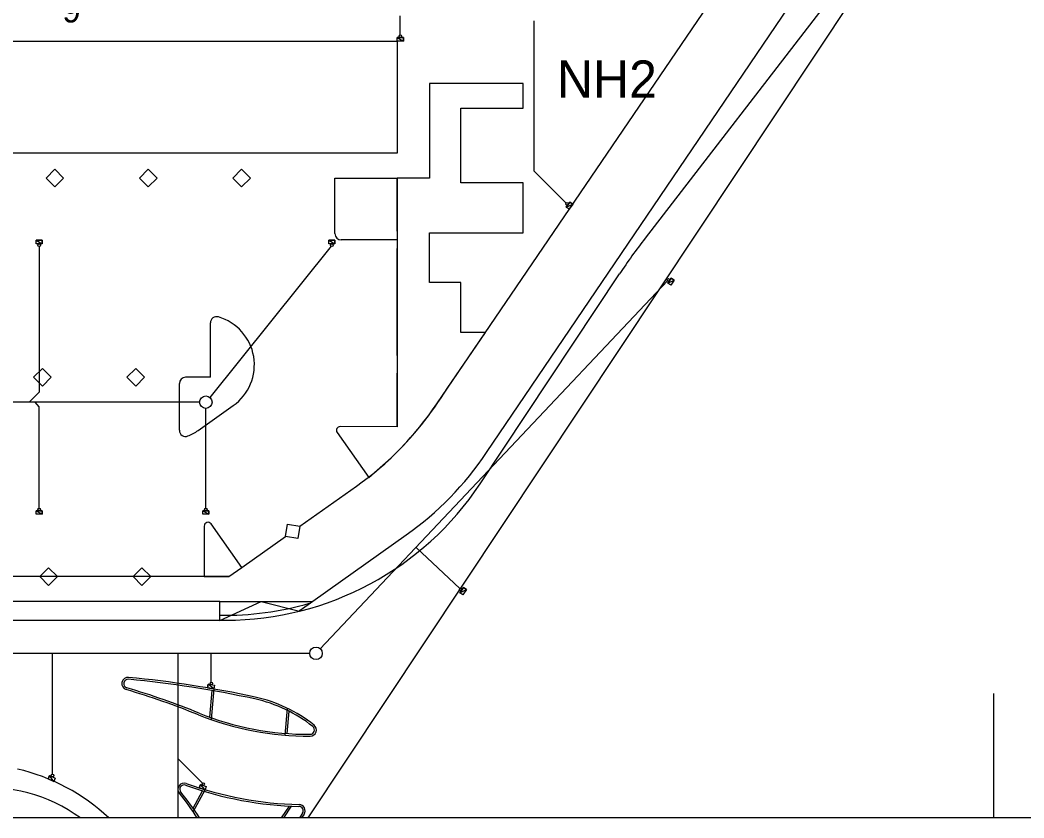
# Model space of a CAD drawing. Extents: x -263964 to -263544, y -1242317 to -1242020.
# Drawn here: x -263832.4 to -263751.7, y -1242317.4 to -1242253.3 of the extents above; entities that cross this region are included whole.
import ezdxf

# ---------------------------------------------------------------- set-up
doc = ezdxf.new("R2010")
doc.units = 0
for name, color, linetype in [('KFA_KOORDINACNA_SITUACIA_DSP_SEDA', 7, 'Continuous'), ('KFA_SO_50-2_POZIARNY_VODOVOD_BODY', 7, 'Continuous'), ('POPIS', 7, 'Continuous'), ('RAM_NA_TLAC_A3_1-100', 7, 'Continuous')]:
    doc.layers.add(name, color=color, linetype=linetype)

msp = doc.modelspace()

# ---------------------------------------------------------------- linework, layer by layer
at = {"layer": 'KFA_KOORDINACNA_SITUACIA_DSP_SEDA'}
for p, q in [((-263798.899, -1242284.125), (-263754.149, -1242218.434)), ((-263794.898, -1242288.032), (-263754.149, -1242227.968)), ((-263809.218, -1242317.359), (-263754.149, -1242234.512)), ((-263754.149, -1242234.482), (-263782.166, -1242270.821)), ((-263801.822, -1242254.497), (-263801.837, -1242252.972)), ((-263791.063, -1242265.427), (-263791.063, -1242253.362)), ((-263802.071, -1242254.697), (-263801.571, -1242254.697)), ((-263802.071, -1242254.987), (-263802.071, -1242254.697)), ((-263802.071, -1242254.697), (-263801.571, -1242254.987)), ((-263802.071, -1242254.697), (-263801.571, -1242254.987)), ((-263801.571, -1242254.697), (-263802.071, -1242254.697)), ((-263801.571, -1242254.987), (-263802.071, -1242254.987)), ((-263801.571, -1242254.697), (-263801.571, -1242254.987)), ((-263801.571, -1242254.987), (-263801.571, -1242254.697)), ((-263788.502, -1242267.989), (-263791.063, -1242265.427)), ((-263807.068, -1242270.447), (-263807.068, -1242265.987)), ((-263807.068, -1242265.987), (-263802.068, -1242265.987)), ((-263802.068, -1242270.24), (-263802.068, -1242265.987)), ((-263788.491, -1242268.322), (-263788.207, -1242267.91)), ((-263788.207, -1242267.91), (-263788.491, -1242268.322)), ((-263788.207, -1242267.91), (-263787.968, -1242268.075)), ((-263787.968, -1242268.075), (-263788.207, -1242267.91)), ((-263788.491, -1242268.322), (-263787.968, -1242268.075)), ((-263788.491, -1242268.322), (-263787.968, -1242268.075)), ((-263788.252, -1242268.487), (-263788.491, -1242268.322)), ((-263787.968, -1242268.075), (-263788.252, -1242268.487)), ((-263831.074, -1242270.983), (-263830.574, -1242270.983)), ((-263831.074, -1242271.273), (-263831.074, -1242270.983)), ((-263831.074, -1242270.983), (-263830.574, -1242271.273)), ((-263831.074, -1242270.983), (-263830.574, -1242271.273)), ((-263830.574, -1242270.983), (-263831.074, -1242270.983)), ((-263830.574, -1242271.273), (-263831.074, -1242271.273)), ((-263830.574, -1242270.983), (-263830.574, -1242271.273)), ((-263830.574, -1242271.273), (-263830.574, -1242270.983)), ((-263807.568, -1242270.982), (-263807.068, -1242270.982)), ((-263807.568, -1242271.272), (-263807.568, -1242270.982)), ((-263807.568, -1242270.982), (-263807.068, -1242271.272)), ((-263807.568, -1242270.982), (-263807.068, -1242271.272)), ((-263807.068, -1242270.982), (-263807.568, -1242270.982)), ((-263807.068, -1242271.272), (-263807.568, -1242271.272)), ((-263807.068, -1242270.982), (-263807.068, -1242271.272)), ((-263807.068, -1242271.272), (-263807.068, -1242270.982)), ((-263802.068, -1242270.947), (-263806.568, -1242270.947)), ((-263830.824, -1242271.473), (-263830.824, -1242283.187)), ((-263807.38, -1242271.45), (-263817.128, -1242283.593)), ((-263802.068, -1242280.24), (-263802.068, -1242271.654)), ((-263795.416, -1242290.541), (-263784.214, -1242273.68)), ((-263780.353, -1242274.236), (-263808.248, -1242303.783)), ((-263780.34, -1242274.426), (-263780.062, -1242274.011)), ((-263780.062, -1242274.011), (-263780.34, -1242274.426)), ((-263780.34, -1242274.426), (-263779.821, -1242274.173)), ((-263780.34, -1242274.426), (-263779.821, -1242274.173)), ((-263780.099, -1242274.588), (-263780.34, -1242274.426)), ((-263779.821, -1242274.173), (-263780.099, -1242274.588)), ((-263780.062, -1242274.011), (-263779.821, -1242274.173)), ((-263779.821, -1242274.173), (-263780.062, -1242274.011)), ((-263817.068, -1242281.982), (-263817.068, -1242277.62)), ((-263802.068, -1242285.947), (-263802.068, -1242281.654)), ((-263819.568, -1242286.231), (-263819.568, -1242282.482)), ((-263817.068, -1242281.982), (-263819.068, -1242281.982)), ((-263830.824, -1242283.187), (-263831.619, -1242283.982)), ((-263817.941, -1242283.982), (-263870.324, -1242283.982)), ((-263817.941, -1242283.982), (-263870.324, -1242283.982)), ((-263830.824, -1242284.343), (-263831.149, -1242283.982)), ((-263830.824, -1242292.492), (-263830.824, -1242284.343)), ((-263818.06, -1242286.248), (-263815.232, -1242284.248)), ((-263817.441, -1242292.492), (-263817.441, -1242284.482)), ((-263809.895, -1242293.947), (-263805.344, -1242290.728)), ((-263831.074, -1242292.693), (-263830.574, -1242292.693)), ((-263831.074, -1242292.983), (-263831.074, -1242292.693)), ((-263831.074, -1242292.693), (-263830.574, -1242292.983)), ((-263831.074, -1242292.693), (-263830.574, -1242292.983)), ((-263830.574, -1242292.693), (-263831.074, -1242292.693)), ((-263830.574, -1242292.983), (-263831.074, -1242292.983)), ((-263830.824, -1242292.693), (-263830.824, -1242292.692)), ((-263830.574, -1242292.693), (-263830.574, -1242292.983)), ((-263830.574, -1242292.983), (-263830.574, -1242292.693)), ((-263817.691, -1242292.692), (-263817.191, -1242292.692)), ((-263817.691, -1242292.982), (-263817.691, -1242292.692)), ((-263817.691, -1242292.692), (-263817.191, -1242292.982)), ((-263817.691, -1242292.692), (-263817.191, -1242292.982)), ((-263817.191, -1242292.692), (-263817.691, -1242292.692)), ((-263817.191, -1242292.982), (-263817.691, -1242292.982)), ((-263817.191, -1242292.692), (-263817.191, -1242292.982)), ((-263817.191, -1242292.982), (-263817.191, -1242292.692)), ((-263809.875, -1242300.669), (-263801.342, -1242294.634)), ((-263814.555, -1242297.242), (-263811.05, -1242294.763)), ((-263797.048, -1242298.952), (-263800.558, -1242295.638)), ((-263815.601, -1242297.982), (-263917.08, -1242297.982)), ((-263797.029, -1242299.286), (-263796.75, -1242298.871)), ((-263796.75, -1242298.871), (-263797.029, -1242299.286)), ((-263797.029, -1242299.286), (-263796.51, -1242299.032)), ((-263797.029, -1242299.286), (-263796.51, -1242299.032)), ((-263796.788, -1242299.448), (-263797.029, -1242299.286)), ((-263796.51, -1242299.032), (-263796.788, -1242299.448)), ((-263796.75, -1242298.871), (-263796.51, -1242299.032)), ((-263796.51, -1242299.032), (-263796.75, -1242298.871)), ((-263816.308, -1242299.982), (-263918.049, -1242299.982)), ((-263816.308, -1242301.482), (-263816.308, -1242299.982)), ((-263816.308, -1242299.982), (-263808.904, -1242299.982)), ((-263809.906, -1242300.757), (-263809.875, -1242300.669)), ((-263914.08, -1242301.482), (-263815.822, -1242301.482)), ((-263809.091, -1242304.153), (-263853.415, -1242304.148)), ((-263829.755, -1242313.856), (-263829.755, -1242304.151)), ((-263819.667, -1242317.359), (-263819.667, -1242304.147)), ((-263817.005, -1242306.465), (-263817.005, -1242304.152)), ((-263817.296, -1242306.914), (-263817.252, -1242306.627)), ((-263817.252, -1242306.627), (-263817.296, -1242306.914)), ((-263817.252, -1242306.627), (-263816.757, -1242306.703)), ((-263816.802, -1242306.99), (-263817.252, -1242306.627)), ((-263816.802, -1242306.99), (-263817.252, -1242306.627)), ((-263816.757, -1242306.703), (-263816.802, -1242306.99)), ((-263816.802, -1242306.99), (-263817.296, -1242306.914)), ((-263817.296, -1242306.914), (-263816.802, -1242306.99)), ((-263816.964, -1242307.132), (-263817.145, -1242309.262)), ((-263816.803, -1242307.008), (-263817.012, -1242309.468)), ((-263810.912, -1242308.547), (-263811.097, -1242310.721)), ((-263810.781, -1242308.779), (-263810.935, -1242310.583)), ((-263817.708, -1242314.574), (-263819.667, -1242312.615)), ((-263830.101, -1242314.219), (-263829.983, -1242313.954)), ((-263829.983, -1242313.954), (-263830.101, -1242314.219)), ((-263829.983, -1242313.954), (-263829.527, -1242314.158)), ((-263829.645, -1242314.423), (-263829.983, -1242313.954)), ((-263829.645, -1242314.423), (-263829.983, -1242313.954)), ((-263829.645, -1242314.423), (-263830.101, -1242314.219)), ((-263830.101, -1242314.219), (-263829.645, -1242314.423)), ((-263829.527, -1242314.158), (-263829.645, -1242314.423)), ((-263817.966, -1242314.94), (-263817.874, -1242314.665)), ((-263817.874, -1242314.665), (-263817.966, -1242314.94)), ((-263817.874, -1242314.665), (-263817.4, -1242314.824)), ((-263817.492, -1242315.099), (-263817.874, -1242314.665)), ((-263817.492, -1242315.099), (-263817.874, -1242314.665)), ((-263818.469, -1242316.58), (-263817.711, -1242315.183)), ((-263818.453, -1242316.866), (-263817.491, -1242315.093)), ((-263817.492, -1242315.099), (-263817.966, -1242314.94)), ((-263817.966, -1242314.94), (-263817.492, -1242315.099)), ((-263817.4, -1242314.824), (-263817.492, -1242315.099)), ((-263810.751, -1242316.405), (-263811.388, -1242317.359)), ((-263810.576, -1242316.414), (-263811.208, -1242317.359)), ((-263809.676, -1242316.98), (-263809.929, -1242317.359)), ((-263809.551, -1242317.064), (-263809.749, -1242317.359))]:
    msp.add_line(p, q, dxfattribs=at)
for points in [[(-263802.068, -1242263.988), (-263834.256, -1242263.984), (-263849.468, -1242254.985), (-263802.068, -1242254.987)], [(-263829.568, -1242265.279), (-263828.861, -1242265.986), (-263829.568, -1242266.693), (-263830.275, -1242265.986)], [(-263822.068, -1242265.279), (-263821.361, -1242265.986), (-263822.068, -1242266.694), (-263822.775, -1242265.986)], [(-263814.568, -1242265.279), (-263813.861, -1242265.986), (-263814.568, -1242266.693), (-263815.275, -1242265.986)], [(-263830.568, -1242281.275), (-263829.861, -1242281.982), (-263830.568, -1242282.689), (-263831.275, -1242281.982)], [(-263823.068, -1242281.275), (-263822.361, -1242281.982), (-263823.068, -1242282.689), (-263823.775, -1242281.982)], [(-263810.881, -1242293.778), (-263809.895, -1242293.947), (-263810.064, -1242294.932), (-263811.05, -1242294.763)], [(-263830.068, -1242297.275), (-263829.361, -1242297.982), (-263830.068, -1242298.689), (-263830.775, -1242297.982)], [(-263822.568, -1242297.275), (-263821.861, -1242297.982), (-263822.568, -1242298.689), (-263823.275, -1242297.982)]]:
    msp.add_lwpolyline(points, close=True, dxfattribs=at)
for points in [[(-263798.064, -1242282.882), (-263794.987, -1242278.383), (-263796.968, -1242278.382), (-263796.968, -1242274.382), (-263799.468, -1242274.382), (-263799.468, -1242270.382), (-263791.968, -1242270.382), (-263791.968, -1242266.382), (-263796.968, -1242266.382), (-263796.968, -1242260.382), (-263791.968, -1242260.382), (-263791.968, -1242258.382), (-263799.468, -1242258.382), (-263799.468, -1242265.987), (-263802.068, -1242265.987)], [(-263802.068, -1242265.987), (-263802.068, -1242270.24), (-263802.068, -1242270.947), (-263802.068, -1242271.654), (-263802.068, -1242273.447), (-263802.068, -1242275.947), (-263802.068, -1242278.447), (-263802.068, -1242280.24), (-263802.068, -1242280.24), (-263802.068, -1242281.654), (-263802.068, -1242283.447), (-263802.068, -1242285.947), (-263806.656, -1242285.943)], [(-263806.901, -1242286.416), (-263804.349, -1242290.024), (-263802.552, -1242288.44)], [(-263817.568, -1242293.926), (-263817.568, -1242297.982), (-263815.601, -1242297.982), (-263814.555, -1242297.242), (-263817.023, -1242293.753)], [(-263816.327, -1242301.51), (-263813.002, -1242299.982), (-263809.906, -1242300.757)]]:
    msp.add_lwpolyline(points, dxfattribs=at)
for centre, radius in [((-263801.821, -1242254.597), 0.1), ((-263788.431, -1242268.059), 0.1), ((-263830.824, -1242271.373), 0.1), ((-263807.318, -1242271.372), 0.1), ((-263780.284, -1242274.163), 0.1), ((-263817.441, -1242283.982), 0.5), ((-263830.824, -1242292.592), 0.1), ((-263817.441, -1242292.592), 0.1), ((-263796.975, -1242299.02), 0.1), ((-263808.591, -1242304.147), 0.5), ((-263817.005, -1242306.565), 0.1), ((-263829.755, -1242313.956), 0.1), ((-263817.637, -1242314.644), 0.1)]:
    msp.add_circle(centre, radius, dxfattribs=at)
for centre, radius, start, end in [((-263806.568, -1242270.447), 0.5, 180, 270), ((-263742.568, -1242301.35), 50, 142.36875, 146.39918), ((-263816.568, -1242277.62), 0.5, 73.84458, 180), ((-263817.542, -1242280.982), 4, 305.27024, 73.84458), ((-263819.068, -1242282.482), 0.5, 90, 180), ((-263821.806, -1242268.304), 27.86, 313.71918, 328.45017), ((-263820.069, -1242269.909), 25.5, 305.27024, 326.11647), ((-263819.068, -1242286.231), 0.5, 180, 291.83316), ((-263820.369, -1242282.982), 4, 291.83316, 305.27024), ((-263806.656, -1242286.243), 0.3, 89.94357, 215.27024), ((-263816.067, -1242273.815), 25.5, 305.27024, 326.11647), ((-263815.822, -1242276.982), 24.5, 270, 326.39918), ((-263817.268, -1242293.926), 0.3, 35.27024, 180), ((-263815.836, -1242276.967), 24.119, 268.87866, 286.17976), ((-263823.686, -1242306.574), 0.5, 84.50312, 253.37264), ((-263823.686, -1242306.574), 0.35, 84.50312, 253.37264), ((-263832, -1242392.966), 87.141, 77.74517, 84.50312), ((-263832, -1242392.966), 87.291, 77.74517, 84.50312), ((-263842.678, -1242370.168), 65.869, 68.01969, 73.37264), ((-263842.678, -1242370.168), 66.019, 68.01969, 73.37264), ((-263815.913, -1242318.902), 11.35, 51.49122, 77.74517), ((-263815.913, -1242318.902), 11.5, 51.49122, 77.74517), ((-263809.228, -1242287.295), 23.5, 248.01969, 270.4085), ((-263809.228, -1242287.295), 23.35, 248.01969, 270.4085), ((-263809.064, -1242310.295), 0.5, 270.4085, 51.49122), ((-263809.064, -1242310.295), 0.35, 270.4085, 51.49122), ((-263836.184, -1242329.025), 16, 46.81331, 76.96946), ((-263819.181, -1242315.066), 0.5, 70.28283, 219.38571), ((-263819.181, -1242315.066), 0.35, 70.28283, 219.38571), ((-263809.228, -1242287.295), 29.15, 250.28283, 268.56407), ((-263809.228, -1242287.295), 29, 250.28283, 268.56407), ((-263835.045, -1242327.715), 12.805, 53.97133, 96.08735), ((-263836.184, -1242329.025), 21.5, 32.86126, 39.38571), ((-263836.184, -1242329.025), 21.65, 32.6052, 39.38571), ((-263809.967, -1242316.786), 0.5, 326.2529, 88.56407), ((-263809.967, -1242316.786), 0.35, 326.2529, 88.56407)]:
    msp.add_arc(centre, radius, start, end, dxfattribs=at)
at = {"layer": 'RAM_NA_TLAC_A3_1-100'}
msp.add_line((-263754.149, -1242317.359), (-263754.149, -1242307.359), dxfattribs=at)
msp.add_lwpolyline([(-263964.149, -1242020.359), (-263544.149, -1242020.359), (-263544.149, -1242317.359), (-263964.149, -1242317.359)], close=True, dxfattribs=at)

# ---------------------------------------------------------------- texts
at = {"layer": 'KFA_SO_50-2_POZIARNY_VODOVOD_BODY'}
msp.add_text('9', height=2, dxfattribs=at).set_placement((-263828.97, -1242253.493))
at = {"layer": 'POPIS'}
msp.add_text('NH2', height=3, dxfattribs=at).set_placement((-263789.241, -1242259.542))

doc.saveas('drawing.dxf')
